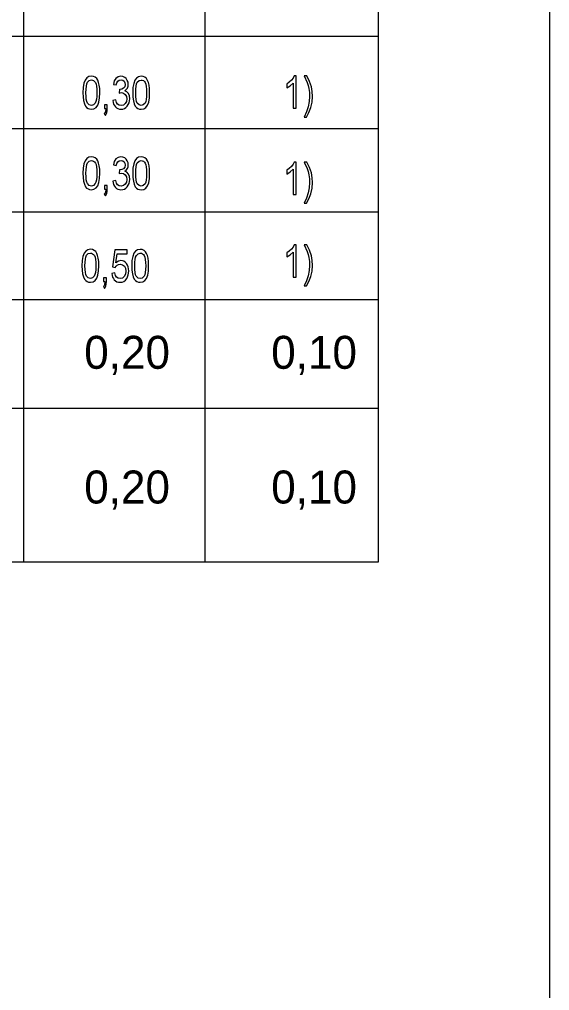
# Model space of a CAD drawing. Extents: x -480568.5 to -480543.1, y -1126945.4 to -1126930.6.
# Drawn here: x -480544.651 to -480543.093, y -1126936.519 to -1126933.666 of the extents above; entities that cross this region are included whole.
import ezdxf

# ---------------------------------------------------------------- set-up
doc = ezdxf.new("R2010")
doc.units = 0
doc.layers.add('detaily', color=7, linetype='Continuous')
doc.layers.add('EL1', color=7, linetype='Continuous')

msp = doc.modelspace()

# ---------------------------------------------------------------- linework, layer by layer
at = {"layer": 'detaily'}
msp.add_line((-480543.0929, -1126930.5663), (-480543.0929, -1126945.4163), dxfattribs=at)
msp.add_lwpolyline([(-480551.8459, -1126935.2592), (-480543.5956, -1126935.2592), (-480543.5956, -1126932.0257), (-480551.8459, -1126932.0257)], close=True, dxfattribs=at)
at = {"layer": 'EL1'}
for p, q in [((-480544.6383, -1126935.2588), (-480544.6383, -1126932.0257)), ((-480544.1063, -1126932.0257), (-480544.1063, -1126935.2588)), ((-480550.8407, -1126933.7155), (-480543.5956, -1126933.7155)), ((-480549.8036, -1126933.9862), (-480543.5956, -1126933.9862)), ((-480550.8351, -1126934.2311), (-480543.5956, -1126934.2311)), ((-480543.5956, -1126934.4894), (-480551.8459, -1126934.4894)), ((-480543.5956, -1126934.8085), (-480551.8459, -1126934.8085))]:
    msp.add_line(p, q, dxfattribs=at)
for points in [[(-480544.4642, -1126933.8812), (-480544.4637, -1126933.8937), (-480544.4623, -1126933.9044), (-480544.46, -1126933.9134), (-480544.4567, -1126933.9207), (-480544.4533, -1126933.9246), (-480544.4493, -1126933.9274), (-480544.4446, -1126933.929), (-480544.4394, -1126933.9296), (-480544.4318, -1126933.9283), (-480544.4256, -1126933.9245), (-480544.4207, -1126933.918), (-480544.4173, -1126933.9086), (-480544.4152, -1126933.8964), (-480544.4145, -1126933.8812), (-480544.4149, -1126933.8686), (-480544.4162, -1126933.8588), (-480544.4181, -1126933.8512), (-480544.4205, -1126933.8447), (-480544.4238, -1126933.8396), (-480544.4282, -1126933.8359), (-480544.4334, -1126933.8335), (-480544.4393, -1126933.8328), (-480544.4469, -1126933.834), (-480544.4531, -1126933.8378), (-480544.4579, -1126933.8444), (-480544.4614, -1126933.8536), (-480544.4635, -1126933.8659)], [(-480544.4554, -1126933.8811), (-480544.4551, -1126933.8708), (-480544.4542, -1126933.8622), (-480544.4527, -1126933.8554), (-480544.4506, -1126933.8503), (-480544.4456, -1126933.8454), (-480544.4394, -1126933.8437), (-480544.436, -1126933.8442), (-480544.4328, -1126933.8456), (-480544.4301, -1126933.8479), (-480544.4277, -1126933.8512), (-480544.4258, -1126933.8558), (-480544.4244, -1126933.8624), (-480544.4235, -1126933.8709), (-480544.4233, -1126933.8812), (-480544.4236, -1126933.8919), (-480544.4244, -1126933.9005), (-480544.4259, -1126933.9071), (-480544.4279, -1126933.9116), (-480544.4331, -1126933.9169), (-480544.4394, -1126933.9186), (-480544.4457, -1126933.9169), (-480544.4508, -1126933.9116), (-480544.4529, -1126933.9071), (-480544.4543, -1126933.9005), (-480544.4551, -1126933.8919)], [(-480544.3765, -1126933.9041), (-480544.3757, -1126933.9095), (-480544.3741, -1126933.9144), (-480544.3719, -1126933.9188), (-480544.3689, -1126933.9226), (-480544.3654, -1126933.9257), (-480544.3615, -1126933.9279), (-480544.3572, -1126933.9293), (-480544.3524, -1126933.9297), (-480544.3471, -1126933.9291), (-480544.3423, -1126933.9275), (-480544.3379, -1126933.9247), (-480544.334, -1126933.9209), (-480544.3309, -1126933.9162), (-480544.3286, -1126933.9111), (-480544.3272, -1126933.9054), (-480544.3268, -1126933.8993), (-480544.3278, -1126933.8906), (-480544.3308, -1126933.8836), (-480544.3355, -1126933.8784), (-480544.3415, -1126933.8753), (-480544.337, -1126933.8719), (-480544.3337, -1126933.8675), (-480544.3317, -1126933.8624), (-480544.3311, -1126933.8567), (-480544.3318, -1126933.8506), (-480544.3338, -1126933.8449), (-480544.3371, -1126933.8399), (-480544.3415, -1126933.8361), (-480544.3469, -1126933.8337), (-480544.3527, -1126933.8329), (-480544.3607, -1126933.8344), (-480544.3673, -1126933.8391), (-480544.3722, -1126933.8466), (-480544.3749, -1126933.8566), (-480544.3662, -1126933.8584), (-480544.3645, -1126933.852), (-480544.3615, -1126933.8475), (-480544.3574, -1126933.8447), (-480544.3523, -1126933.8438), (-480544.3473, -1126933.8448), (-480544.3433, -1126933.8476), (-480544.3407, -1126933.8519), (-480544.3399, -1126933.8571), (-480544.3411, -1126933.8635), (-480544.3447, -1126933.8679), (-480544.3498, -1126933.8705), (-480544.3554, -1126933.8713), (-480544.357, -1126933.8712), (-480544.3581, -1126933.8822), (-480544.3512, -1126933.8809), (-480544.345, -1126933.8822), (-480544.3399, -1126933.8861), (-480544.3366, -1126933.8919), (-480544.3355, -1126933.8992), (-480544.3366, -1126933.9068), (-480544.3399, -1126933.9131), (-480544.3452, -1126933.9173), (-480544.352, -1126933.9187), (-480544.3579, -1126933.9178), (-480544.3623, -1126933.9149), (-480544.3655, -1126933.9098), (-480544.3677, -1126933.9023)], [(-480544.3179, -1126933.8813), (-480544.3175, -1126933.8939), (-480544.3161, -1126933.9046), (-480544.3137, -1126933.9136), (-480544.3104, -1126933.9208), (-480544.307, -1126933.9248), (-480544.303, -1126933.9275), (-480544.2983, -1126933.9292), (-480544.2931, -1126933.9298), (-480544.2855, -1126933.9285), (-480544.2793, -1126933.9246), (-480544.2745, -1126933.9181), (-480544.271, -1126933.9088), (-480544.2689, -1126933.8966), (-480544.2682, -1126933.8814), (-480544.2686, -1126933.8688), (-480544.2699, -1126933.859), (-480544.2718, -1126933.8513), (-480544.2742, -1126933.8449), (-480544.2775, -1126933.8398), (-480544.2819, -1126933.836), (-480544.2871, -1126933.8337), (-480544.293, -1126933.8329), (-480544.3006, -1126933.8342), (-480544.3068, -1126933.838), (-480544.3116, -1126933.8446), (-480544.3151, -1126933.8538), (-480544.3172, -1126933.8661)], [(-480544.3091, -1126933.8813), (-480544.3088, -1126933.871), (-480544.3079, -1126933.8624), (-480544.3064, -1126933.8556), (-480544.3044, -1126933.8505), (-480544.2993, -1126933.8456), (-480544.2931, -1126933.8439), (-480544.2897, -1126933.8444), (-480544.2866, -1126933.8458), (-480544.2838, -1126933.8481), (-480544.2814, -1126933.8513), (-480544.2795, -1126933.856), (-480544.2781, -1126933.8626), (-480544.2773, -1126933.871), (-480544.277, -1126933.8814), (-480544.2773, -1126933.8921), (-480544.2782, -1126933.9007), (-480544.2796, -1126933.9073), (-480544.2816, -1126933.9118), (-480544.2868, -1126933.9171), (-480544.2931, -1126933.9188), (-480544.2994, -1126933.9171), (-480544.3045, -1126933.9118), (-480544.3066, -1126933.9073), (-480544.308, -1126933.9007), (-480544.3089, -1126933.8921)], [(-480543.8376, -1126933.927), (-480543.8374, -1126933.832), (-480543.8431, -1126933.832), (-480543.8464, -1126933.8382), (-480543.8515, -1126933.8446), (-480543.8579, -1126933.8506), (-480543.8652, -1126933.8557), (-480543.8653, -1126933.8669), (-480543.8552, -1126933.8609), (-480543.8462, -1126933.8529), (-480543.8463, -1126933.9269)], [(-480543.8068, -1126933.9526), (-480543.8001, -1126933.9398), (-480543.7944, -1126933.925), (-480543.7905, -1126933.9089), (-480543.7892, -1126933.8923), (-480543.7902, -1126933.8777), (-480543.793, -1126933.8636), (-480543.7986, -1126933.8478), (-480543.8067, -1126933.832), (-480543.814, -1126933.832), (-480543.8054, -1126933.8508), (-480543.8024, -1126933.8597), (-480543.8003, -1126933.8689), (-480543.7986, -1126933.8806), (-480543.798, -1126933.8923), (-480543.799, -1126933.9074), (-480543.8021, -1126933.9225), (-480543.8071, -1126933.9375), (-480543.8141, -1126933.9526)], [(-480544.4013, -1126933.9278), (-480544.397, -1126933.9278), (-480544.3981, -1126933.9374), (-480544.3995, -1126933.9403), (-480544.4014, -1126933.9424), (-480544.3984, -1126933.9479), (-480544.3958, -1126933.9447), (-480544.394, -1126933.9404), (-480544.3929, -1126933.9349), (-480544.3926, -1126933.9278), (-480544.3926, -1126933.9169), (-480544.4013, -1126933.9168)], [(-480544.4642, -1126934.1178), (-480544.4637, -1126934.1303), (-480544.4623, -1126934.1411), (-480544.46, -1126934.1501), (-480544.4567, -1126934.1573), (-480544.4533, -1126934.1612), (-480544.4493, -1126934.164), (-480544.4446, -1126934.1657), (-480544.4394, -1126934.1662), (-480544.4318, -1126934.165), (-480544.4256, -1126934.1611), (-480544.4207, -1126934.1546), (-480544.4173, -1126934.1453), (-480544.4152, -1126934.1331), (-480544.4145, -1126934.1179), (-480544.4149, -1126934.1053), (-480544.4162, -1126934.0955), (-480544.4181, -1126934.0878), (-480544.4205, -1126934.0814), (-480544.4238, -1126934.0763), (-480544.4282, -1126934.0725), (-480544.4334, -1126934.0702), (-480544.4393, -1126934.0694), (-480544.4469, -1126934.0707), (-480544.4531, -1126934.0745), (-480544.4579, -1126934.081), (-480544.4614, -1126934.0903), (-480544.4635, -1126934.1026)], [(-480544.3765, -1126934.1408), (-480544.3757, -1126934.1462), (-480544.3741, -1126934.1511), (-480544.3719, -1126934.1554), (-480544.3689, -1126934.1592), (-480544.3654, -1126934.1624), (-480544.3615, -1126934.1646), (-480544.3572, -1126934.1659), (-480544.3524, -1126934.1664), (-480544.3471, -1126934.1658), (-480544.3423, -1126934.1642), (-480544.3379, -1126934.1614), (-480544.334, -1126934.1575), (-480544.3309, -1126934.1529), (-480544.3286, -1126934.1477), (-480544.3272, -1126934.1421), (-480544.3268, -1126934.1359), (-480544.3278, -1126934.1273), (-480544.3308, -1126934.1202), (-480544.3355, -1126934.115), (-480544.3415, -1126934.1119), (-480544.337, -1126934.1086), (-480544.3337, -1126934.1042), (-480544.3317, -1126934.0991), (-480544.3311, -1126934.0934), (-480544.3318, -1126934.0873), (-480544.3338, -1126934.0816), (-480544.3371, -1126934.0766), (-480544.3415, -1126934.0728), (-480544.3469, -1126934.0704), (-480544.3527, -1126934.0695), (-480544.3607, -1126934.0711), (-480544.3673, -1126934.0757), (-480544.3722, -1126934.0832), (-480544.3749, -1126934.0933), (-480544.3662, -1126934.0951), (-480544.3645, -1126934.0887), (-480544.3615, -1126934.0841), (-480544.3574, -1126934.0814), (-480544.3523, -1126934.0805), (-480544.3473, -1126934.0814), (-480544.3433, -1126934.0843), (-480544.3407, -1126934.0886), (-480544.3399, -1126934.0938), (-480544.3411, -1126934.1001), (-480544.3447, -1126934.1045), (-480544.3498, -1126934.1072), (-480544.3554, -1126934.108), (-480544.357, -1126934.1079), (-480544.3581, -1126934.1189), (-480544.3512, -1126934.1176), (-480544.345, -1126934.1189), (-480544.3399, -1126934.1228), (-480544.3366, -1126934.1286), (-480544.3355, -1126934.1358), (-480544.3366, -1126934.1435), (-480544.3399, -1126934.1498), (-480544.3452, -1126934.154), (-480544.352, -1126934.1554), (-480544.3579, -1126934.1545), (-480544.3623, -1126934.1515), (-480544.3655, -1126934.1465), (-480544.3677, -1126934.1389)], [(-480544.3179, -1126934.118), (-480544.3175, -1126934.1305), (-480544.3161, -1126934.1413), (-480544.3137, -1126934.1503), (-480544.3104, -1126934.1575), (-480544.307, -1126934.1614), (-480544.303, -1126934.1642), (-480544.2983, -1126934.1659), (-480544.2931, -1126934.1664), (-480544.2855, -1126934.1651), (-480544.2793, -1126934.1613), (-480544.2745, -1126934.1548), (-480544.271, -1126934.1455), (-480544.2689, -1126934.1333), (-480544.2682, -1126934.1181), (-480544.2686, -1126934.1054), (-480544.2699, -1126934.0957), (-480544.2718, -1126934.088), (-480544.2742, -1126934.0816), (-480544.2775, -1126934.0765), (-480544.2819, -1126934.0727), (-480544.2871, -1126934.0704), (-480544.293, -1126934.0696), (-480544.3006, -1126934.0709), (-480544.3068, -1126934.0747), (-480544.3116, -1126934.0812), (-480544.3151, -1126934.0905), (-480544.3172, -1126934.1027)], [(-480544.4554, -1126934.1178), (-480544.4551, -1126934.1075), (-480544.4542, -1126934.0989), (-480544.4527, -1126934.092), (-480544.4506, -1126934.0869), (-480544.4456, -1126934.082), (-480544.4394, -1126934.0804), (-480544.436, -1126934.0809), (-480544.4328, -1126934.0822), (-480544.4301, -1126934.0846), (-480544.4277, -1126934.0878), (-480544.4258, -1126934.0925), (-480544.4244, -1126934.0991), (-480544.4235, -1126934.1075), (-480544.4233, -1126934.1179), (-480544.4236, -1126934.1286), (-480544.4244, -1126934.1372), (-480544.4259, -1126934.1438), (-480544.4279, -1126934.1483), (-480544.4331, -1126934.1536), (-480544.4394, -1126934.1553), (-480544.4457, -1126934.1535), (-480544.4508, -1126934.1483), (-480544.4529, -1126934.1438), (-480544.4543, -1126934.1372), (-480544.4551, -1126934.1286)], [(-480544.3091, -1126934.118), (-480544.3088, -1126934.1076), (-480544.3079, -1126934.099), (-480544.3064, -1126934.0922), (-480544.3044, -1126934.0871), (-480544.2993, -1126934.0822), (-480544.2931, -1126934.0806), (-480544.2897, -1126934.0811), (-480544.2866, -1126934.0824), (-480544.2838, -1126934.0848), (-480544.2814, -1126934.088), (-480544.2795, -1126934.0927), (-480544.2781, -1126934.0992), (-480544.2773, -1126934.1077), (-480544.277, -1126934.118), (-480544.2773, -1126934.1288), (-480544.2782, -1126934.1374), (-480544.2796, -1126934.144), (-480544.2816, -1126934.1485), (-480544.2868, -1126934.1537), (-480544.2931, -1126934.1555), (-480544.2994, -1126934.1537), (-480544.3045, -1126934.1485), (-480544.3066, -1126934.144), (-480544.308, -1126934.1374), (-480544.3089, -1126934.1287)], [(-480543.8376, -1126934.1801), (-480543.8374, -1126934.0851), (-480543.8431, -1126934.0851), (-480543.8464, -1126934.0913), (-480543.8515, -1126934.0977), (-480543.8579, -1126934.1037), (-480543.8652, -1126934.1088), (-480543.8653, -1126934.12), (-480543.8552, -1126934.114), (-480543.8462, -1126934.106), (-480543.8463, -1126934.1801)], [(-480543.8068, -1126934.2057), (-480543.8001, -1126934.1929), (-480543.7944, -1126934.1781), (-480543.7905, -1126934.162), (-480543.7892, -1126934.1454), (-480543.7902, -1126934.1308), (-480543.793, -1126934.1168), (-480543.7986, -1126934.1009), (-480543.8067, -1126934.0851), (-480543.814, -1126934.0851), (-480543.8054, -1126934.1039), (-480543.8024, -1126934.1128), (-480543.8003, -1126934.122), (-480543.7986, -1126934.1337), (-480543.798, -1126934.1454), (-480543.799, -1126934.1605), (-480543.8021, -1126934.1756), (-480543.8071, -1126934.1906), (-480543.8141, -1126934.2057)], [(-480544.4013, -1126934.1645), (-480544.397, -1126934.1645), (-480544.3981, -1126934.1741), (-480544.3995, -1126934.177), (-480544.4014, -1126934.1791), (-480544.3984, -1126934.1846), (-480544.3958, -1126934.1814), (-480544.394, -1126934.1771), (-480544.3929, -1126934.1715), (-480544.3926, -1126934.1645), (-480544.3926, -1126934.1535), (-480544.4013, -1126934.1535)], [(-480543.8376, -1126934.4233), (-480543.8374, -1126934.3283), (-480543.8431, -1126934.3283), (-480543.8464, -1126934.3345), (-480543.8515, -1126934.3409), (-480543.8579, -1126934.347), (-480543.8652, -1126934.352), (-480543.8653, -1126934.3632), (-480543.8552, -1126934.3573), (-480543.8462, -1126934.3493), (-480543.8463, -1126934.4233)], [(-480543.8068, -1126934.4489), (-480543.8001, -1126934.4361), (-480543.7944, -1126934.4213), (-480543.7905, -1126934.4053), (-480543.7892, -1126934.3886), (-480543.7902, -1126934.374), (-480543.793, -1126934.36), (-480543.7986, -1126934.3441), (-480543.8067, -1126934.3283), (-480543.814, -1126934.3283), (-480543.8054, -1126934.3472), (-480543.8024, -1126934.356), (-480543.8003, -1126934.3652), (-480543.7986, -1126934.3769), (-480543.798, -1126934.3887), (-480543.799, -1126934.4037), (-480543.8021, -1126934.4188), (-480543.8071, -1126934.4339), (-480543.8141, -1126934.4489)], [(-480544.4671, -1126934.3896), (-480544.4666, -1126934.4021), (-480544.4652, -1126934.4128), (-480544.4629, -1126934.4219), (-480544.4596, -1126934.4291), (-480544.4562, -1126934.433), (-480544.4521, -1126934.4358), (-480544.4475, -1126934.4374), (-480544.4423, -1126934.438), (-480544.4346, -1126934.4367), (-480544.4284, -1126934.4329), (-480544.4236, -1126934.4264), (-480544.4202, -1126934.4171), (-480544.4181, -1126934.4049), (-480544.4174, -1126934.3896), (-480544.4178, -1126934.377), (-480544.4191, -1126934.3672), (-480544.421, -1126934.3596), (-480544.4234, -1126934.3531), (-480544.4266, -1126934.3481), (-480544.431, -1126934.3443), (-480544.4363, -1126934.342), (-480544.4421, -1126934.3412), (-480544.4498, -1126934.3425), (-480544.4559, -1126934.3463), (-480544.4608, -1126934.3528), (-480544.4642, -1126934.3621), (-480544.4663, -1126934.3743)], [(-480544.4583, -1126934.3896), (-480544.458, -1126934.3792), (-480544.4571, -1126934.3706), (-480544.4556, -1126934.3638), (-480544.4535, -1126934.3587), (-480544.4485, -1126934.3538), (-480544.4423, -1126934.3521), (-480544.4388, -1126934.3526), (-480544.4357, -1126934.354), (-480544.433, -1126934.3563), (-480544.4305, -1126934.3596), (-480544.4286, -1126934.3643), (-480544.4272, -1126934.3708), (-480544.4264, -1126934.3793), (-480544.4261, -1126934.3896), (-480544.4264, -1126934.4003), (-480544.4273, -1126934.4089), (-480544.4288, -1126934.4155), (-480544.4308, -1126934.42), (-480544.436, -1126934.4253), (-480544.4423, -1126934.427), (-480544.4485, -1126934.4253), (-480544.4537, -1126934.42), (-480544.4557, -1126934.4155), (-480544.4572, -1126934.4089), (-480544.458, -1126934.4003)], [(-480544.3793, -1126934.4125), (-480544.3785, -1126934.4181), (-480544.3771, -1126934.423), (-480544.3749, -1126934.4273), (-480544.372, -1126934.4311), (-480544.3685, -1126934.4342), (-480544.3646, -1126934.4364), (-480544.3602, -1126934.4377), (-480544.3553, -1126934.4381), (-480544.3494, -1126934.4374), (-480544.3441, -1126934.4353), (-480544.3395, -1126934.4317), (-480544.3356, -1126934.4267), (-480544.333, -1126934.4219), (-480544.3311, -1126934.4166), (-480544.33, -1126934.4109), (-480544.3296, -1126934.4047), (-480544.33, -1126934.3983), (-480544.3313, -1126934.3925), (-480544.3334, -1126934.3873), (-480544.3363, -1126934.3827), (-480544.3399, -1126934.379), (-480544.3439, -1126934.3763), (-480544.3482, -1126934.3747), (-480544.3529, -1126934.3742), (-480544.3601, -1126934.3758), (-480544.3671, -1126934.3805), (-480544.3632, -1126934.3541), (-480544.3339, -1126934.3541), (-480544.3339, -1126934.3431), (-480544.3705, -1126934.3431), (-480544.3778, -1126934.3924), (-480544.3691, -1126934.3942), (-480544.3666, -1126934.3906), (-480544.3636, -1126934.3877), (-480544.3598, -1126934.3858), (-480544.3549, -1126934.3851), (-480544.3475, -1126934.3865), (-480544.3424, -1126934.3906), (-480544.3394, -1126934.397), (-480544.3384, -1126934.4054), (-480544.3395, -1126934.4143), (-480544.3428, -1126934.4212), (-480544.3481, -1126934.4257), (-480544.3553, -1126934.4272), (-480544.3612, -1126934.4261), (-480544.3656, -1126934.423), (-480544.3688, -1126934.4179), (-480544.3705, -1126934.4107)], [(-480544.3208, -1126934.3898), (-480544.3203, -1126934.4023), (-480544.3189, -1126934.413), (-480544.3166, -1126934.422), (-480544.3133, -1126934.4293), (-480544.3099, -1126934.4332), (-480544.3058, -1126934.436), (-480544.3012, -1126934.4376), (-480544.296, -1126934.4382), (-480544.2884, -1126934.4369), (-480544.2821, -1126934.4331), (-480544.2773, -1126934.4266), (-480544.2739, -1126934.4172), (-480544.2718, -1126934.4051), (-480544.2711, -1126934.3898), (-480544.2715, -1126934.3772), (-480544.2728, -1126934.3674), (-480544.2747, -1126934.3598), (-480544.2771, -1126934.3533), (-480544.2803, -1126934.3482), (-480544.2847, -1126934.3445), (-480544.29, -1126934.3421), (-480544.2959, -1126934.3414), (-480544.3035, -1126934.3426), (-480544.3097, -1126934.3464), (-480544.3145, -1126934.353), (-480544.3179, -1126934.3623), (-480544.3201, -1126934.3745)], [(-480544.312, -1126934.3898), (-480544.3117, -1126934.3794), (-480544.3108, -1126934.3708), (-480544.3093, -1126934.364), (-480544.3072, -1126934.3589), (-480544.3022, -1126934.354), (-480544.296, -1126934.3523), (-480544.2925, -1126934.3528), (-480544.2894, -1126934.3542), (-480544.2867, -1126934.3565), (-480544.2843, -1126934.3598), (-480544.2824, -1126934.3644), (-480544.2809, -1126934.371), (-480544.2801, -1126934.3795), (-480544.2798, -1126934.3898), (-480544.2802, -1126934.4005), (-480544.281, -1126934.4091), (-480544.2825, -1126934.4157), (-480544.2845, -1126934.4202), (-480544.2897, -1126934.4255), (-480544.296, -1126934.4272), (-480544.3022, -1126934.4255), (-480544.3074, -1126934.4202), (-480544.3094, -1126934.4157), (-480544.3109, -1126934.4091), (-480544.3117, -1126934.4005)], [(-480544.4042, -1126934.4362), (-480544.3998, -1126934.4362), (-480544.401, -1126934.4458), (-480544.4023, -1126934.4487), (-480544.4042, -1126934.4508), (-480544.4013, -1126934.4563), (-480544.3987, -1126934.4532), (-480544.3969, -1126934.4489), (-480544.3958, -1126934.4433), (-480544.3954, -1126934.4362), (-480544.3954, -1126934.4253), (-480544.4042, -1126934.4253)]]:
    msp.add_lwpolyline(points, close=True, dxfattribs=at)

# ---------------------------------------------------------------- texts
for s, rotation, p in [('0,20', 360, (-480544.4605, -1126934.6922)), ('0,10', 360, (-480543.9109, -1126934.6922)), ('0,20', 0, (-480544.4605, -1126935.0879)), ('0,10', 360, (-480543.9109, -1126935.0879))]:
    msp.add_text(s, height=0.09683, rotation=rotation, dxfattribs=at).set_placement(p)

doc.saveas('drawing.dxf')
